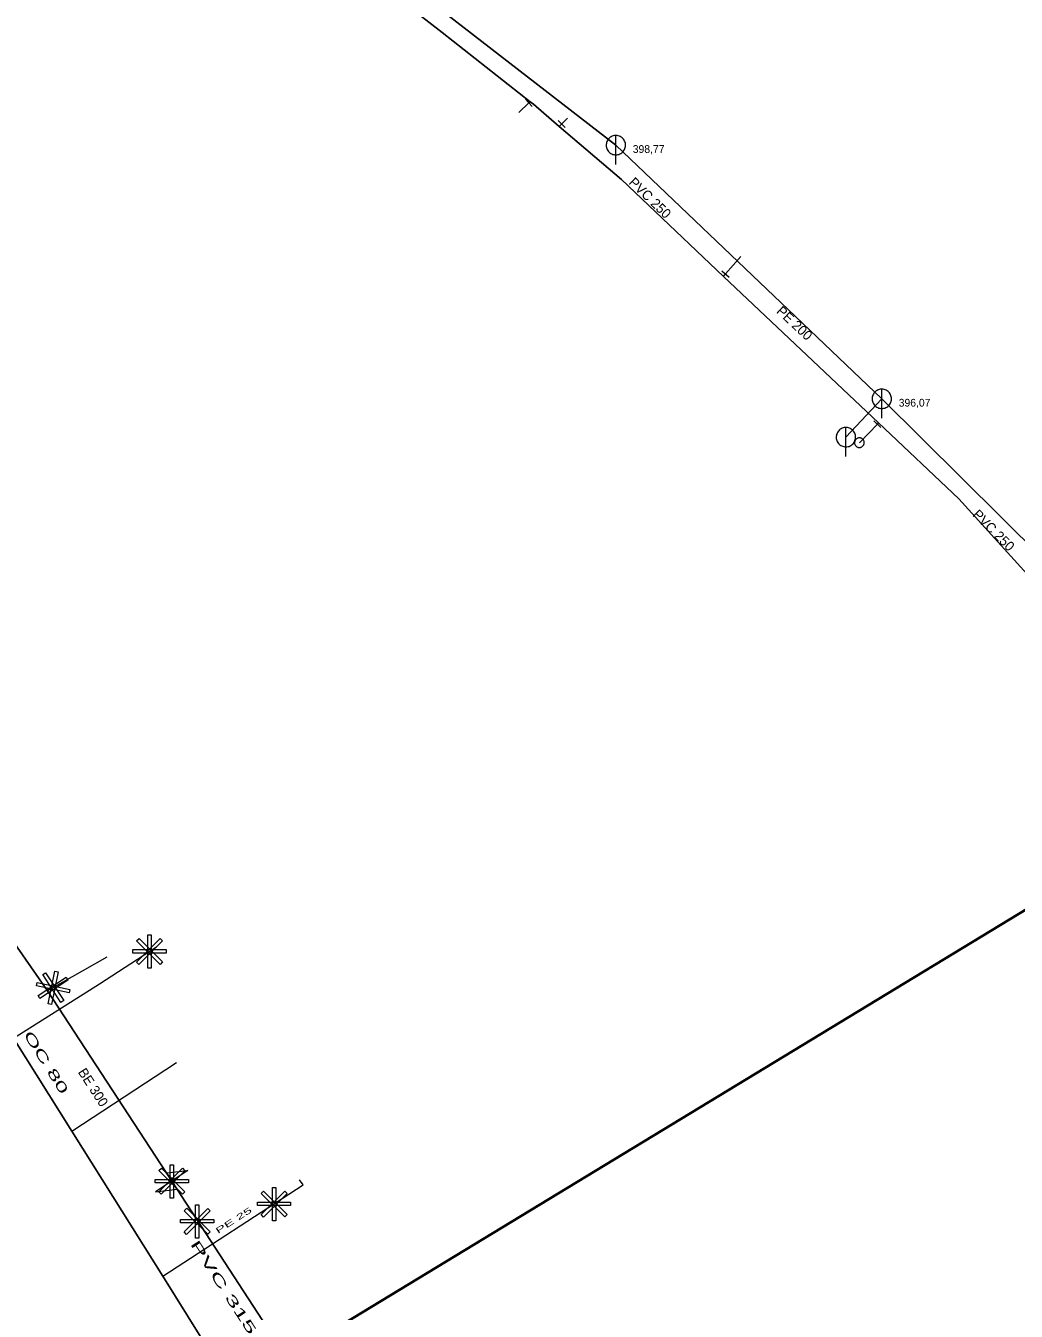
# Model space of a CAD drawing. Extents: x -809028 to -807737, y -990545 to -989489.
# Drawn here: x -808552.3 to -808450.2, y -989956.3 to -989823.8 of the extents above; entities that cross this region are included whole.
import ezdxf

# ---------------------------------------------------------------- set-up
doc = ezdxf.new("R2010")
doc.units = 0
doc.header["$LTSCALE"] = 0.32
for name, color, linetype, lineweight in [('1', 7, 'Continuous', 13), ('10', 7, 'Continuous', 13), ('11', 7, 'Continuous', 13), ('12', 7, 'Continuous', 13), ('13', 7, 'Continuous', 13), ('14', 7, 'Continuous', 25), ('17', 7, 'Continuous', 25), ('22', 7, 'Continuous', 13), ('23', 7, 'Continuous', 13), ('31', 7, 'Continuous', 13), ('34', 7, 'Continuous', 13)]:
    doc.layers.add(name, color=color, linetype=linetype, lineweight=lineweight)

msp = doc.modelspace()

# ---------------------------------------------------------------- linework, layer by layer
at = {"layer": '10'}
for points in [[(-808548.367, -989924.248), (-808548.66, -989924.439), (-808550.538, -989921.563), (-808550.245, -989921.372)], [(-808549.269, -989921.209), (-808548.926, -989921.281), (-808549.632, -989924.643), (-808549.974, -989924.571)], [(-808547.746, -989923.104), (-808547.818, -989923.447), (-808551.18, -989922.742), (-808551.107, -989922.4)], [(-808548.134, -989921.845), (-808547.942, -989922.138), (-808550.818, -989924.017), (-808551.009, -989923.724)], [(-808537.394, -989941.171), (-808537.044, -989941.171), (-808537.044, -989944.606), (-808537.394, -989944.606)], [(-808535.51, -989942.68), (-808535.51, -989943.03), (-808538.945, -989943.03), (-808538.945, -989942.68)], [(-808536.128, -989941.535), (-808535.88, -989941.783), (-808538.309, -989944.212), (-808538.556, -989943.964)], [(-808538.547, -989941.774), (-808538.3, -989941.526), (-808535.871, -989943.955), (-808536.118, -989944.203)], [(-808534.781, -989945.303), (-808534.431, -989945.303), (-808534.431, -989948.738), (-808534.781, -989948.738)], [(-808533.515, -989945.667), (-808533.267, -989945.915), (-808535.696, -989948.344), (-808535.943, -989948.096)], [(-808535.934, -989945.906), (-808535.687, -989945.658), (-808533.258, -989948.087), (-808533.505, -989948.335)], [(-808532.897, -989946.812), (-808532.897, -989947.162), (-808536.332, -989947.162), (-808536.332, -989946.812)]]:
    msp.add_lwpolyline(points, close=True, dxfattribs=at)
at = {"layer": '11'}
for p, q in [((-808467.72, -989866.169), (-808464.02, -989862.219)), ((-808543.938, -989919.759), (-808550.052, -989923.237))]:
    msp.add_line(p, q, dxfattribs=at)
at = {"layer": '12'}
for points in [[(-808539.697, -989917.485), (-808539.347, -989917.485), (-808539.347, -989920.92), (-808539.697, -989920.92)], [(-808538.431, -989917.849), (-808538.183, -989918.097), (-808540.612, -989920.526), (-808540.858, -989920.278)], [(-808540.85, -989918.088), (-808540.603, -989917.84), (-808538.174, -989920.269), (-808538.421, -989920.517)], [(-808537.813, -989918.994), (-808537.813, -989919.344), (-808541.248, -989919.344), (-808541.248, -989918.994)], [(-808525.588, -989943.886), (-808525.34, -989944.134), (-808527.769, -989946.563), (-808528.016, -989946.315)], [(-808528.007, -989944.125), (-808527.76, -989943.877), (-808525.331, -989946.306), (-808525.578, -989946.554)], [(-808526.854, -989943.522), (-808526.504, -989943.522), (-808526.504, -989946.957), (-808526.854, -989946.957)], [(-808524.97, -989945.031), (-808524.97, -989945.381), (-808528.405, -989945.381), (-808528.405, -989945.031)]]:
    msp.add_lwpolyline(points, close=True, dxfattribs=at)
at = {"layer": '13'}
for p, q in [((-808500.399, -989831.709), (-808501.449, -989832.699)), ((-808497.029, -989833.889), (-808496.43, -989833.289)), ((-808480.129, -989849.35), (-808478.559, -989847.559)), ((-808464.479, -989864.829), (-808466.329, -989866.77)), ((-808547.531, -989937.702), (-808536.743, -989930.644))]:
    msp.add_line(p, q, dxfattribs=at)
for points in [[(-808553.532, -989928.12), (-808544.686, -989922.508), (-808538.816, -989918.699)], [(-808538.164, -989952.659), (-808523.673, -989943.245), (-808524.054, -989942.736)]]:
    msp.add_lwpolyline(points, dxfattribs=at)
at = {"layer": '14', "lineweight": 13}
for p, q in [((-808500.399, -989831.709), (-808500.276, -989831.592)), ((-808497.272, -989834.133), (-808497.029, -989833.889)), ((-808480.346, -989849.596), (-808480.129, -989849.35)), ((-808464.479, -989864.829), (-808464.346, -989864.69))]:
    msp.add_line(p, q, dxfattribs=at)
at = {"layer": '14'}
for points in [[(-808522.69, -989811.879), (-808514.37, -989818.319), (-808491.44, -989836.07), (-808464.02, -989862.219)], [(-808464.02, -989862.219), (-808447.57, -989878.53), (-808432, -989901.949)], [(-808564.767, -989901.965), (-808560.398, -989908.392), (-808550.052, -989923.237), (-808537.236, -989942.856)], [(-808537.236, -989942.856), (-808526.347, -989959.525), (-808511.252, -989985.91)]]:
    msp.add_lwpolyline(points, dxfattribs=at)
at = {"layer": '17'}
for points in [[(-808526.899, -989811.259), (-808525.892, -989811.987), (-808518.488, -989817.344), (-808516.993, -989818.511), (-808509.35, -989824.46), (-808500.276, -989831.592), (-808499.949, -989831.85), (-808497.272, -989834.133), (-808490.85, -989839.61), (-808480.346, -989849.596), (-808464.346, -989864.69), (-808456.07, -989872.52), (-808448.02, -989881.399), (-808447.508, -989882.147), (-808441.27, -989891.26), (-808434.44, -989901.129), (-808434.399, -989901.41), (-808435.695, -989906.774)], [(-808597.027, -989858.141), (-808590.285, -989869.403), (-808588.355, -989872.717), (-808579.785, -989886.311), (-808576.531, -989891.473), (-808571.029, -989900.055), (-808568.32, -989904.55), (-808566.73, -989906.969), (-808565.989, -989908.23), (-808563.671, -989911.931), (-808563.097, -989912.848), (-808553.532, -989928.12), (-808547.531, -989937.702), (-808538.164, -989952.659), (-808533.093, -989960.754)]]:
    msp.add_lwpolyline(points, dxfattribs=at)
at = {"layer": '17', "lineweight": 35}
msp.add_lwpolyline([(-808175.378, -990021.169), (-808177.704, -990021.677), (-808294.901, -989877.126), (-808354.054, -989922.417), (-808417.177, -989916.535), (-808426.857, -989907.375), (-808442.53, -989911.14), (-808444.129, -989911.807), (-808534.115, -989966.436)], dxfattribs=at)
at = {"layer": '22'}
for p, q in [((-808491.44, -989838.07), (-808491.439, -989835.07)), ((-808464.02, -989864.219), (-808464.019, -989861.219)), ((-808467.72, -989868.169), (-808467.719, -989865.169))]:
    msp.add_line(p, q, dxfattribs=at)
for points in [[(-808490.44, -989836.07), (-808490.445, -989835.961), (-808490.463, -989835.853), (-808490.493, -989835.747), (-808490.533, -989835.646), (-808490.585, -989835.549), (-808490.647, -989835.459), (-808490.719, -989835.376), (-808490.799, -989835.302), (-808490.887, -989835.236), (-808490.981, -989835.181), (-808491.081, -989835.136), (-808491.186, -989835.103), (-808491.293, -989835.081), (-808491.402, -989835.071), (-808491.512, -989835.073), (-808491.62, -989835.087), (-808491.727, -989835.112), (-808491.83, -989835.149), (-808491.928, -989835.198), (-808492.02, -989835.256), (-808492.106, -989835.325), (-808492.183, -989835.402), (-808492.252, -989835.488), (-808492.311, -989835.58), (-808492.359, -989835.678), (-808492.396, -989835.781), (-808492.422, -989835.888), (-808492.436, -989835.996), (-808492.439, -989836.106), (-808492.429, -989836.215), (-808492.408, -989836.322), (-808492.374, -989836.426), (-808492.33, -989836.526), (-808492.275, -989836.621), (-808492.209, -989836.709), (-808492.135, -989836.789), (-808492.052, -989836.861), (-808491.962, -989836.923), (-808491.866, -989836.975), (-808491.764, -989837.016), (-808491.659, -989837.046), (-808491.551, -989837.064), (-808491.441, -989837.07), (-808491.332, -989837.064), (-808491.224, -989837.046), (-808491.119, -989837.017), (-808491.017, -989836.976), (-808490.92, -989836.924), (-808490.83, -989836.862), (-808490.747, -989836.791), (-808490.672, -989836.711), (-808490.607, -989836.623), (-808490.551, -989836.529), (-808490.507, -989836.429), (-808490.473, -989836.325), (-808490.451, -989836.217), (-808490.441, -989836.108)], [(-808463.02, -989862.219), (-808463.025, -989862.11), (-808463.043, -989862.002), (-808463.073, -989861.896), (-808463.113, -989861.795), (-808463.165, -989861.698), (-808463.227, -989861.608), (-808463.299, -989861.525), (-808463.379, -989861.451), (-808463.467, -989861.385), (-808463.561, -989861.33), (-808463.661, -989861.285), (-808463.766, -989861.252), (-808463.873, -989861.23), (-808463.982, -989861.22), (-808464.092, -989861.222), (-808464.2, -989861.236), (-808464.307, -989861.261), (-808464.41, -989861.298), (-808464.508, -989861.347), (-808464.6, -989861.405), (-808464.686, -989861.474), (-808464.763, -989861.551), (-808464.832, -989861.637), (-808464.891, -989861.729), (-808464.939, -989861.827), (-808464.976, -989861.93), (-808465.002, -989862.037), (-808465.016, -989862.145), (-808465.019, -989862.255), (-808465.009, -989862.364), (-808464.988, -989862.471), (-808464.954, -989862.575), (-808464.91, -989862.675), (-808464.855, -989862.77), (-808464.789, -989862.858), (-808464.715, -989862.938), (-808464.632, -989863.01), (-808464.542, -989863.072), (-808464.446, -989863.124), (-808464.344, -989863.165), (-808464.239, -989863.195), (-808464.131, -989863.213), (-808464.021, -989863.219), (-808463.912, -989863.213), (-808463.804, -989863.195), (-808463.699, -989863.166), (-808463.597, -989863.125), (-808463.5, -989863.073), (-808463.41, -989863.011), (-808463.327, -989862.94), (-808463.252, -989862.86), (-808463.187, -989862.772), (-808463.131, -989862.678), (-808463.087, -989862.578), (-808463.053, -989862.474), (-808463.031, -989862.366), (-808463.021, -989862.257)], [(-808466.72, -989866.169), (-808466.725, -989866.06), (-808466.743, -989865.952), (-808466.773, -989865.846), (-808466.813, -989865.745), (-808466.865, -989865.648), (-808466.927, -989865.558), (-808466.999, -989865.475), (-808467.079, -989865.401), (-808467.167, -989865.335), (-808467.261, -989865.28), (-808467.361, -989865.235), (-808467.466, -989865.202), (-808467.573, -989865.18), (-808467.682, -989865.17), (-808467.792, -989865.172), (-808467.9, -989865.186), (-808468.007, -989865.211), (-808468.11, -989865.248), (-808468.208, -989865.297), (-808468.3, -989865.355), (-808468.386, -989865.424), (-808468.463, -989865.501), (-808468.532, -989865.587), (-808468.591, -989865.679), (-808468.639, -989865.777), (-808468.676, -989865.88), (-808468.702, -989865.987), (-808468.716, -989866.095), (-808468.719, -989866.205), (-808468.709, -989866.314), (-808468.688, -989866.421), (-808468.654, -989866.525), (-808468.61, -989866.625), (-808468.555, -989866.72), (-808468.489, -989866.808), (-808468.415, -989866.888), (-808468.332, -989866.96), (-808468.242, -989867.022), (-808468.146, -989867.074), (-808468.044, -989867.115), (-808467.939, -989867.145), (-808467.831, -989867.163), (-808467.721, -989867.169), (-808467.612, -989867.163), (-808467.504, -989867.145), (-808467.399, -989867.116), (-808467.297, -989867.075), (-808467.2, -989867.023), (-808467.11, -989866.961), (-808467.027, -989866.89), (-808466.952, -989866.81), (-808466.887, -989866.722), (-808466.831, -989866.628), (-808466.787, -989866.528), (-808466.753, -989866.424), (-808466.731, -989866.316), (-808466.721, -989866.207)]]:
    msp.add_lwpolyline(points, close=True, dxfattribs=at)
at = {"layer": '23'}
for points in [[(-808465.875, -989866.947), (-808465.856, -989866.901), (-808465.841, -989866.85), (-808465.833, -989866.797), (-808465.829, -989866.745), (-808465.831, -989866.692), (-808465.838, -989866.641), (-808465.851, -989866.591), (-808465.87, -989866.541), (-808465.892, -989866.495), (-808465.92, -989866.45), (-808465.953, -989866.409), (-808465.988, -989866.371), (-808466.028, -989866.338), (-808466.072, -989866.308), (-808466.118, -989866.283), (-808466.166, -989866.264), (-808466.216, -989866.251), (-808466.268, -989866.241), (-808466.32, -989866.237), (-808466.373, -989866.239), (-808466.425, -989866.247), (-808466.475, -989866.258), (-808466.524, -989866.277), (-808466.571, -989866.299), (-808466.616, -989866.328), (-808466.656, -989866.36), (-808466.694, -989866.396), (-808466.727, -989866.436), (-808466.757, -989866.479), (-808466.782, -989866.526), (-808466.801, -989866.575), (-808466.816, -989866.625), (-808466.825, -989866.676), (-808466.828, -989866.729), (-808466.827, -989866.78), (-808466.82, -989866.832), (-808466.807, -989866.884), (-808466.789, -989866.933), (-808466.766, -989866.98)], [(-808466.425, -989866.247), (-808466.475, -989866.258), (-808466.524, -989866.277), (-808466.571, -989866.299), (-808466.616, -989866.328), (-808466.656, -989866.36), (-808466.694, -989866.396), (-808466.727, -989866.436), (-808466.757, -989866.479), (-808466.782, -989866.526), (-808466.801, -989866.575), (-808466.816, -989866.625), (-808466.825, -989866.676), (-808466.828, -989866.729), (-808466.827, -989866.78), (-808466.82, -989866.832), (-808466.807, -989866.884), (-808466.789, -989866.933), (-808466.766, -989866.98), (-808466.737, -989867.024), (-808466.706, -989867.065), (-808466.67, -989867.103), (-808466.63, -989867.137), (-808466.586, -989867.166), (-808466.54, -989867.189), (-808466.492, -989867.209), (-808466.442, -989867.224), (-808466.389, -989867.232), (-808466.338, -989867.236), (-808466.286, -989867.234), (-808466.234, -989867.227), (-808466.183, -989867.215), (-808466.133, -989867.197), (-808466.086, -989867.174), (-808466.042, -989867.146), (-808466.002, -989867.114), (-808465.964, -989867.079), (-808465.929, -989867.037), (-808465.901, -989866.995), (-808465.875, -989866.947)], [(-808466.766, -989866.98), (-808466.737, -989867.024), (-808466.706, -989867.065), (-808466.67, -989867.103)], [(-808466.67, -989867.103), (-808466.63, -989867.137), (-808466.586, -989867.166), (-808466.54, -989867.189), (-808466.492, -989867.209), (-808466.442, -989867.224), (-808466.389, -989867.232), (-808466.338, -989867.236), (-808466.286, -989867.234), (-808466.234, -989867.227), (-808466.183, -989867.215), (-808466.133, -989867.197), (-808466.086, -989867.174), (-808466.042, -989867.146), (-808466.002, -989867.114), (-808465.964, -989867.079), (-808465.929, -989867.037), (-808465.901, -989866.995), (-808465.875, -989866.947), (-808465.856, -989866.901), (-808465.841, -989866.85), (-808465.833, -989866.797), (-808465.829, -989866.745), (-808465.831, -989866.692), (-808465.838, -989866.641), (-808465.851, -989866.591), (-808465.87, -989866.541), (-808465.892, -989866.495), (-808465.92, -989866.45), (-808465.953, -989866.409), (-808465.988, -989866.371), (-808466.028, -989866.338), (-808466.072, -989866.308), (-808466.118, -989866.283), (-808466.166, -989866.264), (-808466.216, -989866.251), (-808466.268, -989866.241), (-808466.32, -989866.237), (-808466.373, -989866.239), (-808466.425, -989866.247)]]:
    msp.add_lwpolyline(points, dxfattribs=at)
at = {"layer": '31'}
msp.add_lwpolyline([(-808537.783, -989942.019), (-808535.561, -989941.762), (-808538.91, -989943.95), (-808536.689, -989943.693)], dxfattribs=at)
at = {"layer": '34'}
for p, q in [((-808500.742, -989831.345), (-808500.056, -989832.073)), ((-808497.382, -989833.535), (-808496.675, -989834.242)), ((-808480.504, -989849.02), (-808479.753, -989849.68)), ((-808464.841, -989864.484), (-808464.116, -989865.173))]:
    msp.add_line(p, q, dxfattribs=at)

# ---------------------------------------------------------------- texts
at = {"layer": '1'}
for s, rotation, p in [('PVC 250 ', 316, (-808490.187, -989840.006)), ('PE 200', 317, (-808474.961, -989853.287)), ('PVC 250 ', 315, (-808454.723, -989874.232)), ('BE 300', 303, (-808546.946, -989931.62))]:
    msp.add_text(s, height=1, rotation=rotation, dxfattribs=at).set_placement(p)
for s, height, rotation, width, p in [('OC 80 ', 1, 302, 1.9, (-808552.55, -989927.762)), ('PE 25 ', 0.6, 33, 1.95, (-808532.471, -989948.314)), ('PVC 315 ', 1, 303, 2.1, (-808535.367, -989949.346))]:
    msp.add_text(s, height=height, rotation=rotation, dxfattribs=dict(at, width=width)).set_placement(p)
at = {"layer": '14'}
for s, p in [('398,77', (-808489.697, -989836.87)), ('396,07', (-808462.277, -989863.02))]:
    msp.add_text(s, height=0.8, dxfattribs=at).set_placement(p)

doc.saveas('drawing.dxf')
